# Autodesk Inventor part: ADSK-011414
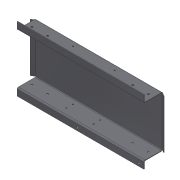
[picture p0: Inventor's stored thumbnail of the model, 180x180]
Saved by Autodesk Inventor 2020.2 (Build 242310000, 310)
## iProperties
Created: 2000-02
Part Number: ADSK-011414
Document SubType Name: Tôlerie
Designer: gpurviance
Material: 1.0312 DC05
Density: 1 g/cm^3
Sheet Metal Rule: Stahlblech 1.0312 - DC05 -   3.0 mm
Appearance: Metal-Steel(Polish)
Mass: 918.035 g
Surface Area: 6204.06 cm^2
Volume: 918.035 cm^3
Sheet Metal Width: 482,793 mm
Sheet Metal Length: 654,043 mm
Sheet Metal Area: 315767,672 mm^2
Flat Pattern Width: 48.2793 cm
Flat Pattern Length: 65.4043 cm
Flat Pattern Area: 3157.68 cm^2
Control State: 0
Master: False
Checked Out: False
Shininess: 57.0
Length Units: 11269
Angle Units: 11279
Time Units: 11290
Mass Units: 11283
Length Display Precision: 3
Angle Display Precision: 2
Compacted: True
Cutlength: 500 SI (19.38 X 25.80)
Material Desc: SHEET,SS,11 GA
Material_Number: A084638
G_L: 482,8x654 mm
Thickness: 3,000 mm
Dimensions: 313,7x92x650,6 mm
Mass: 0,918 kg
Semi finished: Stahlblech 1.0312 - DC05 -   3.0 mm
VLT_Material: 1.0312 DC05
Density: 0.0
Volumn: 0.0
Area: 0.0
PropertySet Name: Model Information
Author: gpurviance
Revision Number: -
Title: ADSK-011414
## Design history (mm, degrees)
node "Face1"
  sketch "Sketch1"
    geometry: L1 (-307.975, -123.825)-(307.975, -123.825); L2 (307.975, -123.825)-(307.975, 123.825); L3 (307.975, 123.825)-(-307.975, 123.825); L4 (-307.975, 123.825)-(-307.975, -123.825); 3 further points
    constraints: 8 end point, 2 midpoint, 2 parallel, 1 horizontal, 1 horizontal alignment, 1 perpendicular, 1 vertical alignment
    dimensions: "Width" = 247.65 distance between parallel lines of L1 L3; "Length" = 615.95 distance between parallel lines of L2 L4
node "Lasche7"
node "Lasche8"
mirror "Spiegeln1"
node "Lasche11"
node "Hole1" dims "d24" = 9, "d25" = 9.525, "d26" = 6.35, "d27" = 60 deg, "d28" = 19.05, "d29" = 118 deg, "d190" = 6
  sketch "Sketch8"
    geometry: L1 (514.95, 46.9)-(590.95, 46.9); L2 (0, -0.1)-(615.95, -0.1) reference; L3 (615.95, 79.9)-(615.95, 5.9) reference
    constraints: 2 end point, 1 horizontal, 1 horizontal alignment
    dimensions: "d187" = 76 distance of L1.start L1.end; "d188" = 47 distance between parallel lines of L1 L2; "d189" = 25 distance from line of L3 L1.end
mirror "Spiegeln2"
node "Hole3" dims "d42" = 9, "d43" = 9.525, "d44" = 6.35, "d45" = 60 deg, "d46" = 19.05, "d47" = 118 deg, "d194" = 6
  sketch "Sketch10"
    geometry: L1 (632.975, -139.75)-(332.975, -139.75); L2 (332.975, -139.75)-(332.975, -431.75); L3 (332.975, -431.75)-(632.975, -431.75); L4 (632.975, -431.75)-(632.975, -139.75); L5 (307.975, -412.575)-(307.975, -442.575) reference; 6 further points
    constraints: 8 end point, 4 coincident, 2 parallel, 1 horizontal, 1 horizontal alignment, 1 midpoint, 1 perpendicular
    dimensions: "d191" = 292 distance of L1.end L2.end; "d192" = 300 distance of L1.start L1.end; "d193" = 25 distance between parallel lines of L5 L2
sketch "Skizze25"
  geometry: L1 (206.475, 59)-(409.475, 59); L2 (409.475, 59)-(409.475, 27); L3 (409.475, 27)-(206.475, 27); L4 (206.475, 27)-(206.475, 59); L5 (0, -6)-(615.95, -6) reference; L6 (1.608, 86)-(614.342, 86) reference; 3 further points
  constraints: 8 end point, 2 midpoint, 2 parallel, 1 horizontal, 1 perpendicular, 1 vertical alignment
  dimensions: "d206" = 203 distance of L2.end L3.end; "d207" = 32 distance of L1.end L2.end; "d217" = 27 distance between parallel lines of L6 L1
hole "Bohrung12" sketch "Skizze25" at (206.475, 59), (206.475, 27), (409.475, 59), (409.475, 27) diameter "d209" = 6.6; stored, may be unused: countersink angle "d213" = 90 deg, drill point angle "d215" = 118 deg; dims "d210" = 6, "d211" = 12.6, "d212" = 2, "d214" = 3 (derived)
sketch "Skizze24"
  geometry: L1 (337, -59)-(206, -59); L2 (206, -59)-(206, -27); L3 (206, -27)-(337, -27); L4 (337, -27)-(337, -59); L5 (0, 0)-(0, -80) reference; L6 (0, 6)-(615.95, 6) reference; L7 (614.342, -86)-(1.608, -86) reference; 1 further point
  constraints: 8 end point, 2 parallel, 1 horizontal, 1 perpendicular
  dimensions: "d195" = 32 distance of L3.end L1.start; "d196" = 131 distance of L1.start L1.end; "d197" = 206 distance between parallel lines of L5 L2; "d216" = 27 distance between parallel lines of L7 L1
hole "Bohrung11" sketch "Skizze24" at (337, -59), (337, -27), (206, -59), (206, -27) diameter "d199" = 6.6; stored, may be unused: countersink angle "d203" = 90 deg, drill point angle "d205" = 118 deg; dims "d200" = 6, "d201" = 12.6, "d202" = 2, "d204" = 3 (derived)
node "Solide1"
node "Corps solides"
node "Corps surfaciques"
node "Plate1" dims "d126" = 3 (derived)
sketch "Skizze18"
  geometry: L1 through (-307.975, 0) direction (1, 0); L2 through (0, 46) direction (0, 1); L3 (0, 92)-(-615.95, 92); L4 (-615.95, 92)-(-615.95, 0)
  constraints: 6 end point, 1 horizontal, 1 perpendicular, 1 vertical
feature "Grobblech8" dims "d126" = 3 (derived), "d127" = 3 (derived), "d128" = 1.5 (derived), "d129" = 6 (derived), "d130" = 3 (derived), "d131" = 92, "d132" = 90 deg, "d133" = 3 (derived), "d134" = 12 (derived), "d135" = 3 (derived), "d136" = 3 (derived), "SeamGap" = 0.00508
feature "Biegung7" dims "d126" = 3 (derived), "d127" = 3 (derived), "d128" = 1.5 (derived), "d129" = 6 (derived), "d130" = 3 (derived), "d131" = 92, "d132" = 90 deg, "d133" = 3 (derived), "SeamGap" = 0.00508
feature "Ecke1" dims "d131" = 92, "d132" = 90 deg, "d134" = 12 (derived), "d135" = 3 (derived), "d136" = 3 (derived)
sketch "Skizze19"
  geometry: L1 through (-307.975, 0) direction (1, -6.34e-34); L2 through (0, 18) direction (6.84e-34, 1); L3 (0, 36)-(-615.95, 36); L4 (-615.95, 36)-(-615.95, 0)
  constraints: 6 end point, 1 horizontal, 1 perpendicular, 1 vertical
feature "Grobblech9" dims "d126" = 3 (derived), "d137" = 3 (derived), "d138" = 1.5 (derived), "d139" = 6 (derived), "d140" = 3 (derived), "d141" = 36, "d142" = 90 deg, "d143" = 3 (derived), "d144" = 12 (derived), "d145" = 3 (derived), "d146" = 3 (derived), "SeamGap" = 0.00508
feature "Biegung8" dims "d126" = 3 (derived), "d137" = 3 (derived), "d138" = 1.5 (derived), "d139" = 6 (derived), "d140" = 3 (derived), "d141" = 36, "d142" = 90 deg, "d143" = 3 (derived), "SeamGap" = 0.00508
feature "Ecke2" dims "d141" = 36, "d142" = 90 deg, "d144" = 12 (derived), "d145" = 3 (derived), "d146" = 3 (derived)
sketch "Skizze22"
  geometry: L1 through (-117.825, 0) direction (1, 0); L2 through (0, 10) direction (0, 1); L3 (0, 20)-(-235.65, 20); L4 (-235.65, 20)-(-235.65, 0)
  constraints: 6 end point, 1 horizontal, 1 perpendicular, 1 vertical
feature "Grobblech12" dims "d126" = 3 (derived), "d167" = 3 (derived), "d168" = 1.5 (derived), "d169" = 6 (derived), "d170" = 3 (derived), "d171" = 20, "d172" = 30 deg, "d173" = 3 (derived), "d174" = 12 (derived), "d175" = 3 (derived), "d176" = 3 (derived), "SeamGap" = 0.00508
feature "Biegung11" dims "d126" = 3 (derived), "d167" = 3 (derived), "d168" = 1.5 (derived), "d169" = 6 (derived), "d170" = 3 (derived), "d171" = 20, "d172" = 30 deg, "d173" = 3 (derived), "SeamGap" = 0.00508
feature "Ecke5" dims "d171" = 20, "d172" = 30 deg, "d174" = 12 (derived), "d175" = 3 (derived), "d176" = 3 (derived)
feature "Definition1"
other parameters: "Thickness" = 3 (derived), "BendRadius" = 3 (derived), "BendReliefWidth" = 3 (derived), "BendReliefDepth" = 1.5 (derived), "CornerReliefSize" = 12 (derived), "MinimumRemnant" = 6 (derived), "d2" = 3 (= BendRadius), "d3" = 85.725, "d4" = 90 deg, "d5" = 3 (= BendRadius), "d9" = 85.725, "d10" = 90 deg, "d11" = 3 (= BendRadius), "d15" = 19.05, "d16" = 30 deg, "d17" = 3 (= BendRadius), "d18" = 19.05, "d19" = 30 deg, "d20" = 3 (= BendRadius), "TransitionRadius" = 3 (derived), "TailleRayonJacobi" = 3 (derived), "TailleJeu" = 3 (derived), "BendRadius" = 3, "BendReliefDepth" = 1.5, "BendReliefWidth" = 3, "CornerReliefSize" = 12, "Length" = 615.95, "MinimumRemnant" = 6, "TailleJeu" = 3, "TailleRayonJacobi" = 3, "Thickness" = 3, "TransitionRadius" = 3, "Width" = 247.65
